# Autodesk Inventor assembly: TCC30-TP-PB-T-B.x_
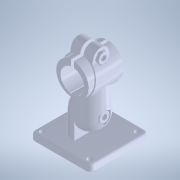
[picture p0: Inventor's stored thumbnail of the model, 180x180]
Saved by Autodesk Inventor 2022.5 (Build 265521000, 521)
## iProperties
Created: 2023-09
Part Number: TCC30-TP-PB-T-B.x_
Document SubType Name: Assembly
Designer: ImaoCorp
Sending System: SOLIDWORKS 2021-2021301
MC: AMD64
MC_MODEL: Intel64 Family 6 Model 60 Stepping 3, GenuineIntel
OS: Windows_NT
FRU: Parasolid Version 32.1, build 255,  1- 1-2021
FORMAT: text
GUISE: transmit
KEY: TCC30-TP-PB-T-B
FILE: TCC30-TP-PB-T-B.x_t
DATE: Fri Sep 15 15:37:40 2023
Author: ImaoCorp
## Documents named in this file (7)
- X:\14_SW2022-Inv2022\00_全2023-1023新製品(TCC)まで\t\tcc30-tp-pb-t-b\TCC30-TP-PB-T-B.iam
- X:\14_SW2022-Inv2022\00_全2023-1023新製品(TCC)まで\t\tcc30-tp-pb-t-b\TCC30-TP-PB-T-B_01.ipt
- X:\14_SW2022-Inv2022\00_全2023-1023新製品(TCC)まで\t\tcc30-tp-pb-t-b\TCC30-TP-PB-T-B_02.ipt
- X:\14_SW2022-Inv2022\00_全2023-1023新製品(TCC)まで\t\tcc30-tp-pb-t-b\TCC30-TP-PB-T-B_03.ipt
- X:\14_SW2022-Inv2022\00_全2023-1023新製品(TCC)まで\t\tcc30-tp-pb-t-b\TCC30-TP-PB-T-B_04.ipt
- X:\14_SW2022-Inv2022\00_全2023-1023新製品(TCC)まで\t\tcc30-tp-pb-t-b\TCC30-TP-PB-T-B_05.ipt
- X:\14_SW2022-Inv2022\00_全2023-1023新製品(TCC)まで\t\tcc30-tp-pb-t-b\TCC30-TP-PB-T-B_06.ipt
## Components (6 placed, 6 different names)
1. TCC30-TP-PB-T-B_01
2. TCC30-TP-PB-T-B_02
3. TCC30-TP-PB-T-B_03
4. TCC30-TP-PB-T-B_04
5. TCC30-TP-PB-T-B_05
6. TCC30-TP-PB-T-B_06
